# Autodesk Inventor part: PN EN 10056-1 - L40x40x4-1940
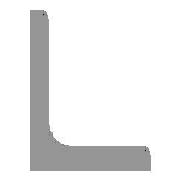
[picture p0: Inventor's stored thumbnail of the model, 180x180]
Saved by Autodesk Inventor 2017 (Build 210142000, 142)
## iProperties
IsCustomPart: 1
Created: 2020-07
Part Number: PN EN 10056-1 - L40x40x4-1940
Material: Stal, miękka
Description: Kątownik równoramienny
Document SubType Name: Modeling
Standard: PN
Designer: X
Standards Organization: PN
Language: pl-PL
Size Designation: L40x40x4
Categories: <MemberInstance><Categories><Category DisplayName="Kształtowniki konstrukcyjne" InternalName="089c4875-fa83-4c05-b084-43b9cc11f5ed" Mnemonic="GRDR"><CategoryPar
Stock Number: L40x40x4
Density: 7.85 g/cm^3
Appearance: Częściowo polerowana
_CCFamilyMember: 70
_CCFamilyDisplayName: PN EN 10056-1 (Kątownik równoramienny) - Kątownik równoramienny
_FrameMemberDoc: Frame Member File
_Version: 15.0.0
_GetPNFromCC: 1
G_L: 1940,000 mm
G_W: 40,000 mm
G_H: 40,000 mm
Author: X
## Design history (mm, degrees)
node "Płaszczyzna początkowa"
node "Płaszczyzna końcowa"
sketch "Szkic2"
  geometry: L1 (-7.249, -1.249)-(-7.249, 25.751); L2 (-11.249, 28.751)-(-10.249, 28.751); L3 (-11.249, -11.249)-(-11.249, 28.751); L4 (-11.249, -11.249)-(28.751, -11.249); L5 (28.751, -10.249)-(28.751, -11.249); L6 (-1.249, -7.249)-(25.751, -7.249); L7 (0, 32.602)-(0, -17.123) reference; L8 (-17.123, 0)-(32.602, 0) reference; A1 r 6 centre (-1.249, -1.249) between (-7.249, -1.249) and (-1.249, -7.249); A2 r 3 centre (-10.249, 25.751) between (-7.249, 25.751) and (-10.249, 28.751); A3 r 3 centre (25.751, -10.249) between (28.751, -10.249) and (25.751, -7.249); 3 further points
  constraints: 12 end point, 6 point on circle, 6 point on line, 6 tangent, 3 centre point, 3 horizontal, 3 vertical, 1 equal radius
  dimensions: "d4" = 40 distance of L3.start L4.end (= b); "d6" = 40 distance of L3.start L2.start (= b); "d8" = 4 distance of point (28.751, -7.249) L4.end (= ParT); "d10" = 4 distance of L2.start point (-7.249, 28.751) (= ParT); "d17" = 6 radius of A1 (= R); "d18" = 3 radius of A2 (= R1); "d19" = 11.24871 distance between parallel lines of L8 L4 (= ex); "d20" = 11.24871 distance between parallel lines of L3 L7 (= d19)
extrude "Bryła" new body sketch "Szkic2" stored distance "d11" = 1940 (= G_L); taper "d12" = 0 deg
node "Driven Length"
  sketch "Sketch3"
    geometry: L1 (0, 0)-(10, 0) reference
    constraints: 2 end point, 1 horizontal
  workplane "Work Plane10"
  sketch "Sketch4"
    geometry: L1 (-2, 0)-(12, 0) reference; L2 (-2, 1940)-(12, 1940) reference
    dimensions: "d24" = 1940 distance between parallel lines of L1 L2 (derived)
body "Solid1"
other parameters: "b" = 40 [user parameter; used in 3 equation terms], "ParT" = 4 [user parameter; used in 3 equation terms], "R" = 6 [user parameter; used in 1 equation term], "R1" = 3 [user parameter; used in 1 equation term], "G_L" = 1940 (= d24) [user parameter; used in 1 equation term], "d7" = 4 (derived), "d9" = 4 (derived), "ex" = 11.24871 (computed from b, ParT) [user parameter; used in 1 equation term], "G_OFFSET_START" = 0 [user parameter; used in 1 equation term], "G_OFFSET_END" = 0 [user parameter; used in 1 equation term], "d21" = 0 (computed from G_OFFSET_START), "d23" = 90 deg
